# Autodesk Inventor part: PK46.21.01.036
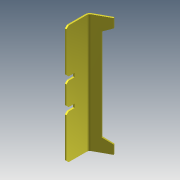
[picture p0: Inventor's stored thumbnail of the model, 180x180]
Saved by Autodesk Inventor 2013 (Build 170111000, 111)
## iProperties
Created: 2005-04
Part Number: PK46.21.01.036
Material: Steel, Mild
Document SubType Name: Sheet Metal
Designer: salex
Manufacturer: Standard
Standards Organization: Custom
Density: 7.86 g/cm^3
Sheet Metal Rule: Default
Author: salex
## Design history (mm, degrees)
node "ФлнОтгиб1"
sketch "Эскиз2"
  geometry: L1 (0, 0)-(800, 0) reference; L2 (800, 0)-(800, 138.127) reference; L3 (297, 0)-(322, 0); L4 (322, 0)-(322, 55); L5 (322, 55)-(297, 55); L6 (297, 55)-(297, 0); L7 (477, 0)-(502, 0); L8 (502, 0)-(502, 55); L9 (502, 55)-(477, 55); L10 (477, 55)-(477, 0)
  constraints: 16 end point, 4 parallel, 2 collinear, 2 horizontal, 2 perpendicular, 2 point on line
  dimensions: "d10" = 298 distance between parallel lines of L8 L2; "d11" = 25 distance of L8.end L9.end; "d12" = 55 distance of L7.end L8.end; "d13" = 180 distance between parallel lines of L4 L8
extrude "Выдавливание1" cut sketch "Эскиз2" stored distance "d14" = 10; taper "d15" = 0 deg
feature "Угловая фаска1" dims "d16" = 15, "d17" = 6, angle "d18" = 45 deg
sketch "Эскиз3"
  geometry: L1 (-113.427, 0)-(0, 0) reference; L2 (0, 800)-(0, 0) reference; L3 (0, 800)-(-113.427, 800) reference; L4 (0, 740)-(-60, 710); L5 (-60, 710)-(-60, 90); L6 (-60, 90)-(0, 60)
  constraints: 6 end point, 2 point on line, 1 equal length, 1 perpendicular
  dimensions: "d19" = 60 distance from line of L4.start L3; "d20" = 60 distance from line of L6.end L1; "d21" = 90 distance from line of L4.end L3; "d22" = 60 distance between parallel lines of L2 L5
extrude "Выдавливание2" cut sketch "Эскиз3" stored distance "d23" = 10; taper "d24" = 0 deg
body "Solid1"
sketch "Эскиз1"
  geometry: L1 (0, 0)-(0, 150); L2 (0, 150)-(110, 210)
  constraints: 4 end point, 1 vertical, 1 other
  dimensions: "d0" = 150 distance of L1.start L1.end; "d1" = 210 vertical distance of L2.end L1.start; "d2" = 110 horizontal distance of L1.end L2.end
feature "Плакирование1" dims "d3" = 800, "d4" = 10 (= BendReliefWidth), "d6" = 20 (= MinimumRemnant), "d8" = 20 (= BendRadius), "d9" = 10, "Thickness" = 10
feature "Изгиб1" dims "d4" = 10 (= BendReliefWidth), "d5" = 5 (= BendReliefDepth), "d6" = 20 (= MinimumRemnant), "d7" = 20 (= BendRadius), "d8" = 20 (= BendRadius), "d9" = 10, "SeamGap" = 0.01, "Thickness" = 10
other parameters: "BendRadius" = 20, "BendReliefDepth" = 5 (= 0.5 x Thickness)
